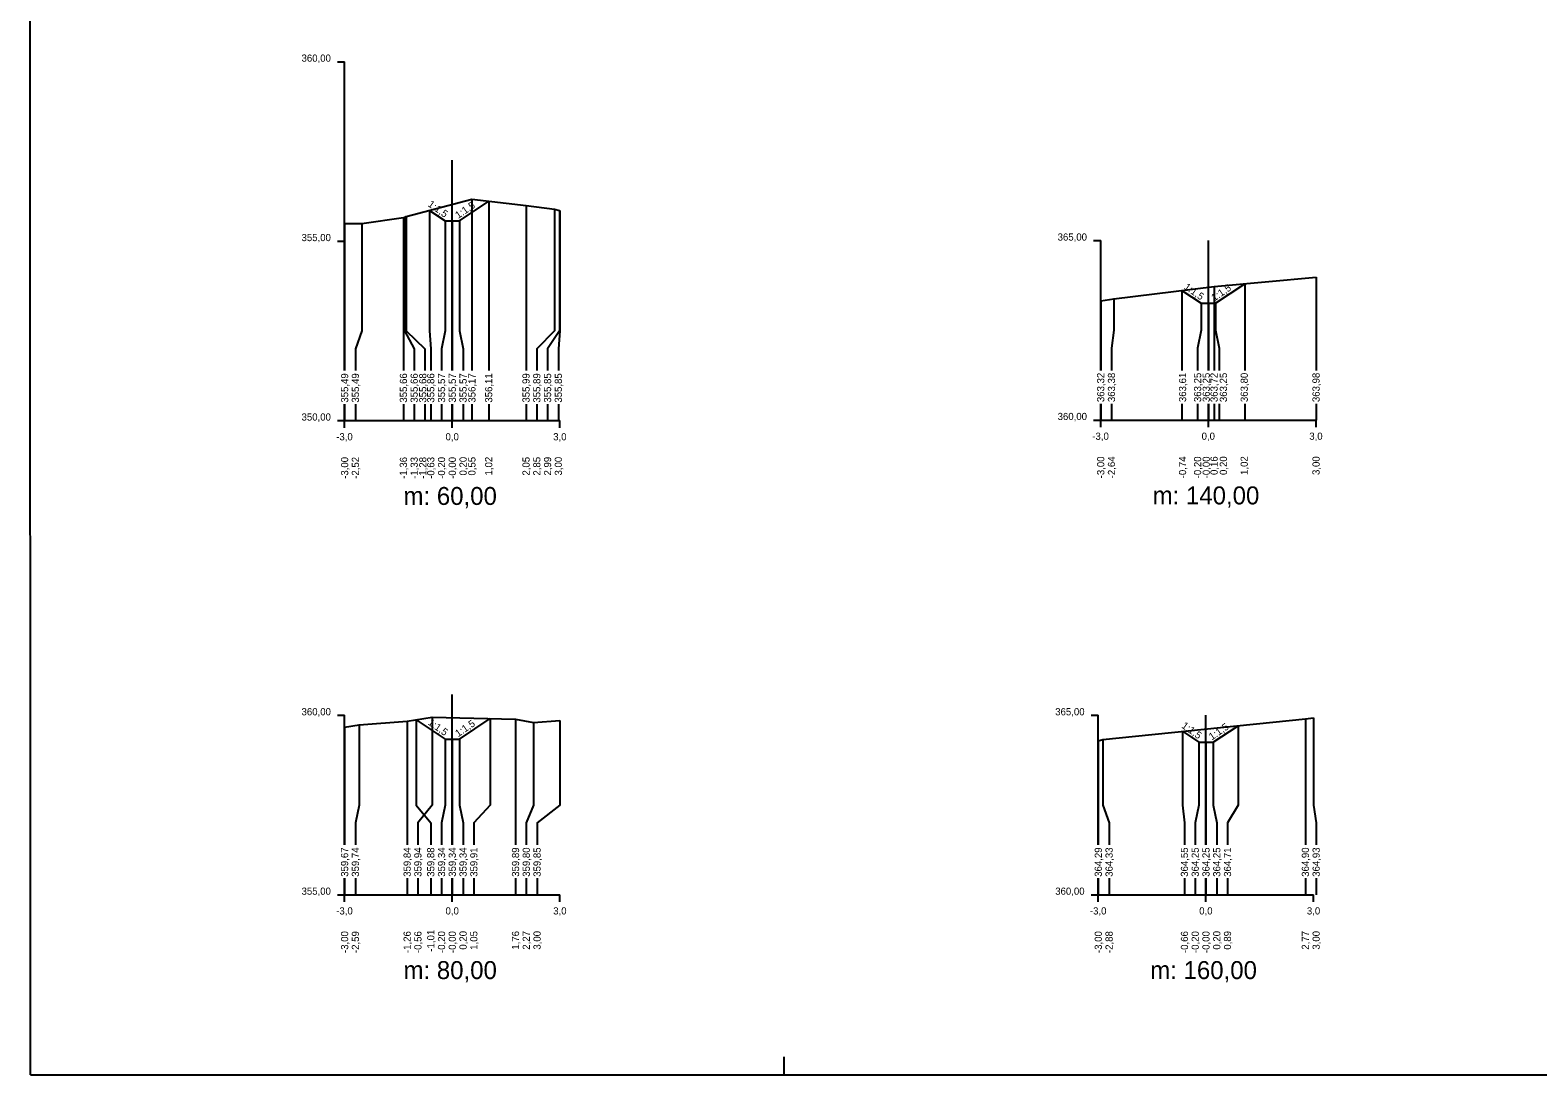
# Model space of a CAD drawing. Extents: x -497367.2 to -497283.2, y -1136708.7 to -1136649.3.
# Drawn here: x -497367.25 to -497325.24, y -1136708.74 to -1136679.63 of the extents above; entities that cross this region are included whole.
import ezdxf

# ---------------------------------------------------------------- set-up
doc = ezdxf.new("R2010")
doc.units = 0
for name, color, linetype in [('11', 7, 'Continuous'), ('16', 7, 'Continuous'), ('21', 7, 'Continuous'), ('28', 7, 'Continuous'), ('59', 7, 'Continuous'), ('8', 7, 'Continuous'), ('Vrstva 63', 7, 'Continuous')]:
    doc.layers.add(name, color=color, linetype=linetype)

msp = doc.modelspace()

# ---------------------------------------------------------------- linework, layer by layer
for points in [[(-497358.486, -1136685.016), (-497358.008, -1136685.018), (-497356.848, -1136684.852), (-497356.82, -1136684.846), (-497356.77, -1136684.823), (-497354.939, -1136684.34), (-497353.431, -1136684.519), (-497352.641, -1136684.621), (-497352.497, -1136684.656), (-497352.486, -1136684.656)], [(-497356.119, -1136684.651), (-497355.686, -1136684.94), (-497355.486, -1136684.94), (-497355.286, -1136684.94), (-497354.47, -1136684.396)], [(-497355.686, -1136684.942), (-497355.686, -1136684.94), (-497355.686, -1136684.937)], [(-497355.286, -1136684.942), (-497355.286, -1136684.94), (-497355.286, -1136684.937)], [(-497337.419, -1136687.174), (-497337.056, -1136687.115), (-497334.261, -1136686.774), (-497331.419, -1136686.513)], [(-497335.155, -1136686.883), (-497334.619, -1136687.241), (-497334.419, -1136687.241), (-497334.219, -1136687.241), (-497333.401, -1136686.695)], [(-497334.619, -1136687.241), (-497334.619, -1136687.241), (-497334.619, -1136687.241)], [(-497334.219, -1136687.241), (-497334.219, -1136687.241), (-497334.219, -1136687.241)], [(-497358.486, -1136699.054), (-497358.081, -1136698.982), (-497356.744, -1136698.879), (-497356.044, -1136698.776), (-497353.724, -1136698.827), (-497353.219, -1136698.92), (-497352.486, -1136698.866)], [(-497356.494, -1136698.842), (-497355.686, -1136699.381), (-497355.486, -1136699.381), (-497355.286, -1136699.381), (-497354.433, -1136698.812)], [(-497337.486, -1136699.428), (-497337.362, -1136699.391), (-497331.716, -1136698.818), (-497331.486, -1136698.795)], [(-497335.143, -1136699.166), (-497334.686, -1136699.471), (-497334.486, -1136699.471), (-497334.286, -1136699.471), (-497333.593, -1136699.009)], [(-497333.593, -1136699.009), (-497333.593, -1136699.009), (-497333.593, -1136699.008)], [(-497355.686, -1136699.382), (-497355.686, -1136699.381), (-497355.686, -1136699.379)], [(-497355.286, -1136699.382), (-497355.286, -1136699.381), (-497355.286, -1136699.379)], [(-497335.143, -1136699.167), (-497335.143, -1136699.166), (-497335.143, -1136699.165)], [(-497334.686, -1136699.471), (-497334.686, -1136699.471), (-497334.686, -1136699.47)], [(-497334.286, -1136699.471), (-497334.286, -1136699.471), (-497334.286, -1136699.47)]]:
    msp.add_lwpolyline(points)
at = {"layer": '11'}
for points in [[(-497354.939, -1136684.34), (-497354.939, -1136688.008), (-497354.939, -1136688.508), (-497354.939, -1136689.114)], [(-497354.47, -1136684.396), (-497354.47, -1136689.114)], [(-497356.77, -1136684.823), (-497356.77, -1136688.008), (-497356.248, -1136688.508), (-497356.248, -1136689.114)], [(-497356.119, -1136684.651), (-497356.119, -1136688.008), (-497356.086, -1136688.508), (-497356.086, -1136689.114)], [(-497353.431, -1136684.519), (-497353.431, -1136688.008), (-497353.431, -1136688.508), (-497353.431, -1136689.114)], [(-497352.641, -1136684.621), (-497352.641, -1136688.008), (-497353.131, -1136688.508), (-497353.131, -1136689.114)], [(-497352.497, -1136684.656), (-497352.497, -1136688.008), (-497352.831, -1136688.508), (-497352.831, -1136689.114)], [(-497352.486, -1136684.656), (-497352.486, -1136688.008), (-497352.531, -1136688.508), (-497352.531, -1136689.114)], [(-497358.486, -1136685.016), (-497358.486, -1136688.008), (-497358.486, -1136688.508), (-497358.486, -1136689.114)], [(-497358.008, -1136685.018), (-497358.008, -1136688.008), (-497358.186, -1136688.508), (-497358.186, -1136689.114)], [(-497356.848, -1136684.852), (-497356.848, -1136688.008), (-497356.848, -1136688.508), (-497356.848, -1136689.114)], [(-497356.82, -1136684.846), (-497356.82, -1136688.008), (-497356.548, -1136688.508), (-497356.548, -1136689.114)], [(-497355.686, -1136684.94), (-497355.686, -1136688.008), (-497355.786, -1136688.508), (-497355.786, -1136689.114)], [(-497355.486, -1136684.94), (-497355.486, -1136688.008), (-497355.486, -1136688.508), (-497355.486, -1136689.114)], [(-497355.286, -1136684.94), (-497355.286, -1136688.008), (-497355.186, -1136688.508), (-497355.186, -1136689.114)], [(-497331.419, -1136686.513), (-497331.419, -1136687.993), (-497331.419, -1136688.493), (-497331.419, -1136689.109)], [(-497335.155, -1136686.883), (-497335.155, -1136689.109)], [(-497334.261, -1136686.774), (-497334.261, -1136687.993), (-497334.261, -1136688.493), (-497334.261, -1136689.109)], [(-497333.401, -1136686.695), (-497333.401, -1136689.109)], [(-497337.419, -1136687.174), (-497337.419, -1136687.993), (-497337.419, -1136688.493), (-497337.419, -1136689.109)], [(-497337.056, -1136687.115), (-497337.056, -1136687.993), (-497337.119, -1136688.493), (-497337.119, -1136689.109)], [(-497334.619, -1136687.241), (-497334.619, -1136687.993), (-497334.719, -1136688.493), (-497334.719, -1136689.109)], [(-497334.419, -1136687.241), (-497334.419, -1136687.993), (-497334.419, -1136688.493), (-497334.419, -1136689.109)], [(-497334.219, -1136687.241), (-497334.219, -1136687.993), (-497334.119, -1136688.493), (-497334.119, -1136689.109)], [(-497358.486, -1136690.048), (-497358.486, -1136690.508)], [(-497358.186, -1136690.048), (-497358.186, -1136690.508)], [(-497356.848, -1136690.048), (-497356.848, -1136690.508)], [(-497356.548, -1136690.048), (-497356.548, -1136690.508)], [(-497356.248, -1136690.048), (-497356.248, -1136690.508)], [(-497356.086, -1136690.048), (-497356.086, -1136690.508)], [(-497355.786, -1136690.048), (-497355.786, -1136690.508)], [(-497355.486, -1136690.048), (-497355.486, -1136690.508)], [(-497355.186, -1136690.048), (-497355.186, -1136690.508)], [(-497354.939, -1136690.048), (-497354.939, -1136690.508)], [(-497354.47, -1136690.048), (-497354.47, -1136690.508)], [(-497353.431, -1136690.048), (-497353.431, -1136690.508)], [(-497353.131, -1136690.048), (-497353.131, -1136690.508)], [(-497352.831, -1136690.048), (-497352.831, -1136690.508)], [(-497352.531, -1136690.048), (-497352.531, -1136690.508)], [(-497337.419, -1136690.044), (-497337.419, -1136690.493)], [(-497337.119, -1136690.044), (-497337.119, -1136690.493)], [(-497335.155, -1136690.044), (-497335.155, -1136690.493)], [(-497334.719, -1136690.044), (-497334.719, -1136690.493)], [(-497334.419, -1136690.044), (-497334.419, -1136690.493)], [(-497334.261, -1136690.044), (-497334.261, -1136690.493)], [(-497334.119, -1136690.044), (-497334.119, -1136690.493)], [(-497333.401, -1136690.044), (-497333.401, -1136690.493)], [(-497331.419, -1136690.044), (-497331.419, -1136690.493)], [(-497358.486, -1136699.054), (-497358.486, -1136701.22), (-497358.486, -1136701.72), (-497358.486, -1136702.325)], [(-497358.081, -1136698.982), (-497358.081, -1136701.22), (-497358.186, -1136701.72), (-497358.186, -1136702.325)], [(-497356.744, -1136698.879), (-497356.744, -1136701.22), (-497356.744, -1136701.72), (-497356.744, -1136702.325)], [(-497356.494, -1136698.842), (-497356.494, -1136701.22), (-497356.086, -1136701.72), (-497356.086, -1136702.325)], [(-497356.044, -1136698.776), (-497356.044, -1136701.22), (-497356.444, -1136701.72), (-497356.444, -1136702.325)], [(-497354.433, -1136698.812), (-497354.433, -1136701.22), (-497354.886, -1136701.72), (-497354.886, -1136702.325)], [(-497353.724, -1136698.827), (-497353.724, -1136701.22), (-497353.724, -1136701.72), (-497353.724, -1136702.325)], [(-497353.219, -1136698.92), (-497353.219, -1136701.22), (-497353.424, -1136701.72), (-497353.424, -1136702.325)], [(-497352.486, -1136698.866), (-497352.486, -1136701.22), (-497353.124, -1136701.72), (-497353.124, -1136702.325)], [(-497333.593, -1136699.009), (-497333.593, -1136701.22), (-497333.886, -1136701.72), (-497333.886, -1136702.325)], [(-497331.716, -1136698.818), (-497331.716, -1136701.22), (-497331.716, -1136701.72), (-497331.716, -1136702.325)], [(-497331.486, -1136698.795), (-497331.486, -1136701.22), (-497331.416, -1136701.72), (-497331.416, -1136702.325)], [(-497355.686, -1136699.381), (-497355.686, -1136701.22), (-497355.786, -1136701.72), (-497355.786, -1136702.325)], [(-497355.486, -1136699.381), (-497355.486, -1136701.22), (-497355.486, -1136701.72), (-497355.486, -1136702.325)], [(-497355.286, -1136699.381), (-497355.286, -1136701.22), (-497355.186, -1136701.72), (-497355.186, -1136702.325)], [(-497337.486, -1136699.428), (-497337.486, -1136701.22), (-497337.486, -1136701.72), (-497337.486, -1136702.325)], [(-497337.362, -1136699.391), (-497337.362, -1136701.22), (-497337.186, -1136701.72), (-497337.186, -1136702.325)], [(-497335.143, -1136699.166), (-497335.143, -1136701.22), (-497335.086, -1136701.72), (-497335.086, -1136702.325)], [(-497334.686, -1136699.471), (-497334.686, -1136701.22), (-497334.786, -1136701.72), (-497334.786, -1136702.325)], [(-497334.486, -1136699.471), (-497334.486, -1136701.22), (-497334.486, -1136701.72), (-497334.486, -1136702.325)], [(-497334.286, -1136699.471), (-497334.286, -1136701.22), (-497334.186, -1136701.72), (-497334.186, -1136702.325)], [(-497358.486, -1136703.259), (-497358.486, -1136703.72)], [(-497358.186, -1136703.259), (-497358.186, -1136703.72)], [(-497356.744, -1136703.259), (-497356.744, -1136703.72)], [(-497356.444, -1136703.259), (-497356.444, -1136703.72)], [(-497356.086, -1136703.259), (-497356.086, -1136703.72)], [(-497355.786, -1136703.259), (-497355.786, -1136703.72)], [(-497355.486, -1136703.259), (-497355.486, -1136703.72)], [(-497355.186, -1136703.259), (-497355.186, -1136703.72)], [(-497354.886, -1136703.259), (-497354.886, -1136703.72)], [(-497353.724, -1136703.259), (-497353.724, -1136703.72)], [(-497353.424, -1136703.259), (-497353.424, -1136703.72)], [(-497353.124, -1136703.259), (-497353.124, -1136703.72)], [(-497337.486, -1136703.259), (-497337.486, -1136703.72)], [(-497337.186, -1136703.259), (-497337.186, -1136703.72)], [(-497335.086, -1136703.259), (-497335.086, -1136703.72)], [(-497334.786, -1136703.259), (-497334.786, -1136703.72)], [(-497334.486, -1136703.259), (-497334.486, -1136703.72)], [(-497334.186, -1136703.259), (-497334.186, -1136703.72)], [(-497333.886, -1136703.259), (-497333.886, -1136703.72)], [(-497331.716, -1136703.259), (-497331.716, -1136703.72)], [(-497331.416, -1136703.259), (-497331.416, -1136703.72)]]:
    msp.add_lwpolyline(points, dxfattribs=at)
at = {"layer": '16'}
for p, q in [((-497358.486, -1136690.508), (-497352.486, -1136690.508)), ((-497337.419, -1136690.493), (-497331.419, -1136690.493)), ((-497358.486, -1136703.72), (-497352.486, -1136703.72)), ((-497337.486, -1136703.72), (-497331.486, -1136703.72))]:
    msp.add_line(p, q, dxfattribs=at)
for points in [[(-497355.486, -1136684.942), (-497355.486, -1136684.94), (-497355.486, -1136684.937)], [(-497334.419, -1136687.241), (-497334.419, -1136687.241), (-497334.419, -1136687.241)], [(-497355.486, -1136699.382), (-497355.486, -1136699.381), (-497355.486, -1136699.379)], [(-497334.486, -1136699.471), (-497334.486, -1136699.471), (-497334.486, -1136699.47)]]:
    msp.add_lwpolyline(points, dxfattribs=at)
at = {"layer": '21'}
for p, q in [((-497358.686, -1136680.508), (-497358.486, -1136680.508)), ((-497358.686, -1136685.508), (-497358.486, -1136685.508)), ((-497337.619, -1136685.493), (-497337.419, -1136685.493)), ((-497358.686, -1136690.508), (-497358.486, -1136690.508)), ((-497337.619, -1136690.493), (-497337.419, -1136690.493)), ((-497358.686, -1136698.72), (-497358.486, -1136698.72)), ((-497337.686, -1136698.72), (-497337.486, -1136698.72)), ((-497358.686, -1136703.72), (-497358.486, -1136703.72)), ((-497337.686, -1136703.72), (-497337.486, -1136703.72))]:
    msp.add_line(p, q, dxfattribs=at)
at = {"layer": '28'}
for p, q in [((-497355.486, -1136689.114), (-497355.486, -1136683.248)), ((-497334.419, -1136689.109), (-497334.419, -1136685.493)), ((-497355.486, -1136690.508), (-497355.486, -1136690.048)), ((-497334.419, -1136690.493), (-497334.419, -1136690.044)), ((-497355.486, -1136702.325), (-497355.486, -1136698.145)), ((-497334.486, -1136702.325), (-497334.486, -1136698.72)), ((-497355.486, -1136703.72), (-497355.486, -1136703.259)), ((-497334.486, -1136703.72), (-497334.486, -1136703.259))]:
    msp.add_line(p, q, dxfattribs=at)
at = {"layer": '59'}
for p, q in [((-497358.486, -1136690.708), (-497358.486, -1136690.508)), ((-497355.486, -1136690.708), (-497355.486, -1136690.508)), ((-497352.486, -1136690.708), (-497352.486, -1136690.508)), ((-497337.419, -1136690.693), (-497337.419, -1136690.493)), ((-497334.419, -1136690.693), (-497334.419, -1136690.493)), ((-497331.419, -1136690.693), (-497331.419, -1136690.493)), ((-497358.486, -1136703.92), (-497358.486, -1136703.72)), ((-497355.486, -1136703.92), (-497355.486, -1136703.72)), ((-497352.486, -1136703.92), (-497352.486, -1136703.72)), ((-497337.486, -1136703.92), (-497337.486, -1136703.72)), ((-497334.486, -1136703.92), (-497334.486, -1136703.72)), ((-497331.486, -1136703.92), (-497331.486, -1136703.72))]:
    msp.add_line(p, q, dxfattribs=at)
at = {"layer": '8'}
for p, q in [((-497358.486, -1136689.114), (-497358.486, -1136680.508)), ((-497337.419, -1136689.109), (-497337.419, -1136685.493)), ((-497358.486, -1136690.508), (-497358.486, -1136690.048)), ((-497337.419, -1136690.493), (-497337.419, -1136690.044)), ((-497358.486, -1136702.325), (-497358.486, -1136698.72)), ((-497337.486, -1136702.325), (-497337.486, -1136698.72)), ((-497358.486, -1136703.72), (-497358.486, -1136703.259)), ((-497337.486, -1136703.72), (-497337.486, -1136703.259))]:
    msp.add_line(p, q, dxfattribs=at)
at = {"layer": 'Vrstva 63'}
for p, q in [((-497367.238, -1136708.736), (-497367.248, -1136649.335)), ((-497346.238, -1136708.738), (-497346.238, -1136708.241)), ((-497367.238, -1136708.736), (-497283.238, -1136708.735))]:
    msp.add_line(p, q, dxfattribs=at)

# ---------------------------------------------------------------- texts
at = {"layer": '16'}
for s, p in [('355,49', (-497358.386, -1136690.008)), ('355,49', (-497358.086, -1136690.008)), ('355,66', (-497356.748, -1136690.008)), ('355,66', (-497356.448, -1136690.008)), ('355,68', (-497356.209, -1136690.008)), ('355,86', (-497355.986, -1136690.008)), ('355,57', (-497355.686, -1136690.008)), ('355,57', (-497355.386, -1136690.008)), ('355,57', (-497355.086, -1136690.008)), ('356,17', (-497354.839, -1136690.008)), ('356,11', (-497354.372, -1136690.008)), ('355,99', (-497353.331, -1136690.008)), ('355,89', (-497353.031, -1136690.008)), ('355,85', (-497352.731, -1136690.008)), ('355,85', (-497352.431, -1136690.008)), ('363,32', (-497337.319, -1136689.993)), ('363,38', (-497337.019, -1136689.993)), ('363,61', (-497335.038, -1136689.993)), ('363,25', (-497334.619, -1136689.993)), ('363,25', (-497334.379, -1136689.993)), ('363,72', (-497334.161, -1136689.993)), ('363,25', (-497333.901, -1136689.993)), ('363,80', (-497333.32, -1136689.993)), ('363,98', (-497331.319, -1136689.993)), ('359,67', (-497358.386, -1136703.22)), ('359,74', (-497358.086, -1136703.22)), ('359,84', (-497356.644, -1136703.22)), ('359,94', (-497356.344, -1136703.22)), ('359,88', (-497355.986, -1136703.22)), ('359,34', (-497355.686, -1136703.22)), ('359,34', (-497355.386, -1136703.22)), ('359,34', (-497355.086, -1136703.22)), ('359,91', (-497354.786, -1136703.22)), ('359,89', (-497353.624, -1136703.22)), ('359,80', (-497353.324, -1136703.22)), ('359,85', (-497353.024, -1136703.22)), ('364,29', (-497337.386, -1136703.22)), ('364,33', (-497337.086, -1136703.22)), ('364,55', (-497334.986, -1136703.22)), ('364,25', (-497334.686, -1136703.22)), ('364,25', (-497334.386, -1136703.22)), ('364,25', (-497334.086, -1136703.22)), ('364,71', (-497333.786, -1136703.22)), ('364,90', (-497331.616, -1136703.22)), ('364,93', (-497331.316, -1136703.22))]:
    msp.add_text(s, height=0.2, rotation=90, dxfattribs=at).set_placement(p)
at = {"layer": '21'}
for s, p in [('360,00', (-497359.686, -1136680.508)), ('355,00', (-497359.686, -1136685.508)), ('365,00', (-497338.619, -1136685.493)), ('350,00', (-497359.686, -1136690.508)), ('360,00', (-497338.619, -1136690.493)), ('-3,0', (-497358.72, -1136691.058)), ('0,0', (-497355.674, -1136691.058)), ('3,0', (-497352.674, -1136691.058)), ('-3,0', (-497337.653, -1136691.043)), ('0,0', (-497334.607, -1136691.043)), ('3,0', (-497331.607, -1136691.043)), ('360,00', (-497359.686, -1136698.72)), ('365,00', (-497338.686, -1136698.72)), ('355,00', (-497359.686, -1136703.72)), ('360,00', (-497338.686, -1136703.72)), ('-3,0', (-497358.72, -1136704.27)), ('0,0', (-497355.674, -1136704.27)), ('3,0', (-497352.674, -1136704.27)), ('-3,0', (-497337.72, -1136704.27)), ('0,0', (-497334.674, -1136704.27)), ('3,0', (-497331.674, -1136704.27))]:
    msp.add_text(s, height=0.2, dxfattribs=at).set_placement(p)
for rotation, p in [(324.91, (-497356.183, -1136684.522)), (34.4489, (-497355.32, -1136684.891)), (324.91, (-497335.116, -1136686.823)), (34.4489, (-497334.252, -1136687.192)), (324.91, (-497356.183, -1136698.963)), (34.4489, (-497355.32, -1136699.332)), (324.91, (-497335.183, -1136699.052)), (34.4489, (-497334.32, -1136699.422))]:
    msp.add_text('1:1,5', height=0.2, rotation=rotation, dxfattribs=at).set_placement(p)
at = {"layer": '28'}
for s, p in [('m: 60,00', (-497356.845, -1136692.858)), ('m: 140,00', (-497335.972, -1136692.843)), ('m: 80,00', (-497356.845, -1136706.07)), ('m: 160,00', (-497336.039, -1136706.07))]:
    msp.add_text(s, height=0.5, dxfattribs=at).set_placement(p)
at = {"layer": '59'}
for s, p in [('-3,00', (-497358.386, -1136692.131)), ('-2,52', (-497358.086, -1136692.13)), ('-1,36', (-497356.748, -1136692.132)), ('-1,33', (-497356.448, -1136692.132)), ('-1,28', (-497356.209, -1136692.132)), ('-0,63', (-497355.986, -1136692.132)), ('-0,20', (-497355.686, -1136692.131)), ('-0,00', (-497355.386, -1136692.131)), ('0,20', (-497355.086, -1136692.038)), ('0,55', (-497354.839, -1136692.04)), ('1,02', (-497354.372, -1136692.037)), ('2,05', (-497353.331, -1136692.04)), ('2,85', (-497353.031, -1136692.04)), ('2,99', (-497352.731, -1136692.039)), ('3,00', (-497352.431, -1136692.038)), ('-3,00', (-497337.319, -1136692.117)), ('-2,64', (-497337.019, -1136692.116)), ('-0,74', (-497335.038, -1136692.116)), ('-0,20', (-497334.619, -1136692.117)), ('-0,00', (-497334.379, -1136692.117)), ('0,16', (-497334.161, -1136692.024)), ('0,20', (-497333.901, -1136692.024)), ('1,02', (-497333.32, -1136692.022)), ('3,00', (-497331.319, -1136692.024)), ('-3,00', (-497358.386, -1136705.343)), ('-2,59', (-497358.086, -1136705.344)), ('-1,26', (-497356.644, -1136705.344)), ('-0,56', (-497356.344, -1136705.344)), ('-1,01', (-497355.986, -1136705.305)), ('-0,20', (-497355.686, -1136705.343)), ('-0,00', (-497355.386, -1136705.343)), ('0,20', (-497355.086, -1136705.25)), ('1,05', (-497354.786, -1136705.253)), ('1,76', (-497353.624, -1136705.251)), ('2,27', (-497353.324, -1136705.251)), ('3,00', (-497353.024, -1136705.25)), ('-3,00', (-497337.386, -1136705.343)), ('-2,88', (-497337.086, -1136705.344)), ('-0,66', (-497334.986, -1136705.344)), ('-0,20', (-497334.686, -1136705.343)), ('-0,00', (-497334.386, -1136705.343)), ('0,20', (-497334.086, -1136705.25)), ('0,89', (-497333.786, -1136705.251)), ('2,77', (-497331.616, -1136705.251)), ('3,00', (-497331.316, -1136705.25))]:
    msp.add_text(s, height=0.2, rotation=90, dxfattribs=at).set_placement(p)

doc.saveas('drawing.dxf')
